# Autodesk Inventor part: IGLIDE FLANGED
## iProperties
Shininess: 50.0
Length Units: 11272
Angle Units: 11279
Time Units: 11290
Mass Units: 11286
Length Display Precision: 3
Angle Display Precision: 2
Part Number: IGLIDE FLANGED
Document SubType Name: Modeling
Created: 2003-08
Material: Delrin, Black
Designer: CM
Manufacturer: Standard
Standards Organization: Custom
Description: IGUS IGLIDE® BEARING, FLANGED
Density: 10.49
Volumn: 2.304646865681294
Area: 8.437628188859923
PropertySet Name: Model Information
Control State: 0
Master: False
Checked Out: False
Author: CM
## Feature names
1. Revolution2
2. Revolution3
